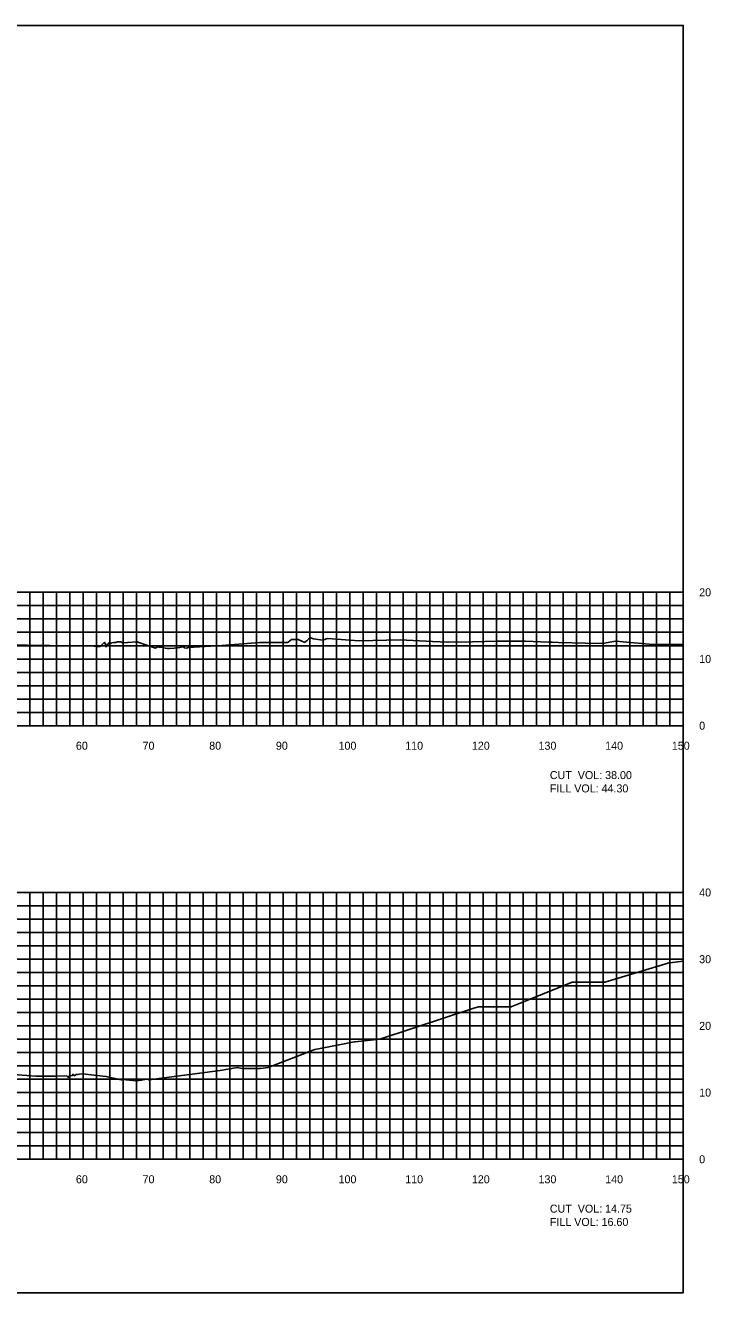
# Model space of a CAD drawing. Extents: x 1797645 to 1803805, y 248417 to 250269.
# Drawn here: x 1803702.3 to 1803805.1, y 250079.4 to 250269.4 of the extents above; entities that cross this region are included whole.
import ezdxf

# ---------------------------------------------------------------- set-up
doc = ezdxf.new("R2010")
doc.units = 0
for name, color, linetype in [('10', 7, 'Continuous'), ('31', 7, 'Continuous'), ('60', 7, 'Continuous'), ('ANNO-TXT', 7, 'Continuous'), ('Level 62', 7, 'Continuous'), ('M-ROADS', 7, 'Continuous')]:
    doc.layers.add(name, color=color, linetype=linetype)

msp = doc.modelspace()

# ---------------------------------------------------------------- linework, layer by layer
msp.add_lwpolyline([(1803501, 250079.43), (1803801, 250079.43), (1803801, 250269.43), (1803501, 250269.43)], close=True)
at = {"layer": '60'}
for p, q in [((1803801, 250164.43), (1803801, 250184.43)), ((1803801.06, 250184.43), (1803801, 250184.43)), ((1803801.06, 250174.43), (1803801, 250174.43)), ((1803501, 250164.43), (1803801, 250164.43)), ((1803711, 250164.37), (1803711, 250164.43)), ((1803721, 250164.37), (1803721, 250164.43)), ((1803731, 250164.37), (1803731, 250164.43)), ((1803741, 250164.37), (1803741, 250164.43)), ((1803751, 250164.37), (1803751, 250164.43)), ((1803761, 250164.37), (1803761, 250164.43)), ((1803771, 250164.37), (1803771, 250164.43)), ((1803781, 250164.37), (1803781, 250164.43)), ((1803791, 250164.37), (1803791, 250164.43)), ((1803801, 250164.37), (1803801, 250164.43)), ((1803801.06, 250164.43), (1803801, 250164.43)), ((1803801, 250099.43), (1803801, 250139.43)), ((1803801.06, 250139.43), (1803801, 250139.43)), ((1803801.06, 250129.43), (1803801, 250129.43)), ((1803801.06, 250119.43), (1803801, 250119.43)), ((1803801.06, 250109.43), (1803801, 250109.43)), ((1803501, 250099.43), (1803801, 250099.43)), ((1803711, 250099.37), (1803711, 250099.43)), ((1803721, 250099.37), (1803721, 250099.43)), ((1803731, 250099.37), (1803731, 250099.43)), ((1803741, 250099.37), (1803741, 250099.43)), ((1803751, 250099.37), (1803751, 250099.43)), ((1803761, 250099.37), (1803761, 250099.43)), ((1803771, 250099.37), (1803771, 250099.43)), ((1803781, 250099.37), (1803781, 250099.43)), ((1803791, 250099.37), (1803791, 250099.43)), ((1803801, 250099.37), (1803801, 250099.43)), ((1803801.06, 250099.43), (1803801, 250099.43))]:
    msp.add_line(p, q, dxfattribs=at)
at = {"layer": 'Level 62'}
for p, q in [((1803501, 250184.43), (1803801, 250184.43)), ((1803703, 250164.43), (1803703, 250184.43)), ((1803705, 250164.43), (1803705, 250184.43)), ((1803707, 250164.43), (1803707, 250184.43)), ((1803709, 250164.43), (1803709, 250184.43)), ((1803711, 250164.43), (1803711, 250184.43)), ((1803713, 250164.43), (1803713, 250184.43)), ((1803715, 250164.43), (1803715, 250184.43)), ((1803717, 250164.43), (1803717, 250184.43)), ((1803719, 250164.43), (1803719, 250184.43)), ((1803721, 250164.43), (1803721, 250184.43)), ((1803723, 250164.43), (1803723, 250184.43)), ((1803725, 250164.43), (1803725, 250184.43)), ((1803727, 250164.43), (1803727, 250184.43)), ((1803729, 250164.43), (1803729, 250184.43)), ((1803731, 250164.43), (1803731, 250184.43)), ((1803733, 250164.43), (1803733, 250184.43)), ((1803735, 250164.43), (1803735, 250184.43)), ((1803737, 250164.43), (1803737, 250184.43)), ((1803739, 250164.43), (1803739, 250184.43)), ((1803741, 250164.43), (1803741, 250184.43)), ((1803743, 250164.43), (1803743, 250184.43)), ((1803745, 250164.43), (1803745, 250184.43)), ((1803747, 250164.43), (1803747, 250184.43)), ((1803749, 250164.43), (1803749, 250184.43)), ((1803751, 250164.43), (1803751, 250184.43)), ((1803753, 250164.43), (1803753, 250184.43)), ((1803755, 250164.43), (1803755, 250184.43)), ((1803757, 250164.43), (1803757, 250184.43)), ((1803759, 250164.43), (1803759, 250184.43)), ((1803761, 250164.43), (1803761, 250184.43)), ((1803763, 250164.43), (1803763, 250184.43)), ((1803765, 250164.43), (1803765, 250184.43)), ((1803767, 250164.43), (1803767, 250184.43)), ((1803769, 250164.43), (1803769, 250184.43)), ((1803771, 250164.43), (1803771, 250184.43)), ((1803773, 250164.43), (1803773, 250184.43)), ((1803775, 250164.43), (1803775, 250184.43)), ((1803777, 250164.43), (1803777, 250184.43)), ((1803779, 250164.43), (1803779, 250184.43)), ((1803781, 250164.43), (1803781, 250184.43)), ((1803783, 250164.43), (1803783, 250184.43)), ((1803785, 250164.43), (1803785, 250184.43)), ((1803787, 250164.43), (1803787, 250184.43)), ((1803789, 250164.43), (1803789, 250184.43)), ((1803791, 250164.43), (1803791, 250184.43)), ((1803793, 250164.43), (1803793, 250184.43)), ((1803795, 250164.43), (1803795, 250184.43)), ((1803797, 250164.43), (1803797, 250184.43)), ((1803799, 250164.43), (1803799, 250184.43)), ((1803801, 250164.43), (1803801, 250184.43)), ((1803501, 250182.43), (1803801, 250182.43)), ((1803501, 250180.43), (1803801, 250180.43)), ((1803501, 250178.43), (1803801, 250178.43)), ((1803501, 250176.43), (1803801, 250176.43)), ((1803501, 250174.43), (1803801, 250174.43)), ((1803501, 250172.43), (1803801, 250172.43)), ((1803501, 250170.43), (1803801, 250170.43)), ((1803501, 250168.43), (1803801, 250168.43)), ((1803501, 250166.43), (1803801, 250166.43)), ((1803501, 250164.43), (1803801, 250164.43)), ((1803501, 250139.43), (1803801, 250139.43)), ((1803703, 250099.43), (1803703, 250139.43)), ((1803705, 250099.43), (1803705, 250139.43)), ((1803707, 250099.43), (1803707, 250139.43)), ((1803709, 250099.43), (1803709, 250139.43)), ((1803711, 250099.43), (1803711, 250139.43)), ((1803713, 250099.43), (1803713, 250139.43)), ((1803715, 250099.43), (1803715, 250139.43)), ((1803717, 250099.43), (1803717, 250139.43)), ((1803719, 250099.43), (1803719, 250139.43)), ((1803721, 250099.43), (1803721, 250139.43)), ((1803723, 250099.43), (1803723, 250139.43)), ((1803725, 250099.43), (1803725, 250139.43)), ((1803727, 250099.43), (1803727, 250139.43)), ((1803729, 250099.43), (1803729, 250139.43)), ((1803731, 250099.43), (1803731, 250139.43)), ((1803733, 250099.43), (1803733, 250139.43)), ((1803735, 250099.43), (1803735, 250139.43)), ((1803737, 250099.43), (1803737, 250139.43)), ((1803739, 250099.43), (1803739, 250139.43)), ((1803741, 250099.43), (1803741, 250139.43)), ((1803743, 250099.43), (1803743, 250139.43)), ((1803745, 250099.43), (1803745, 250139.43)), ((1803747, 250099.43), (1803747, 250139.43)), ((1803749, 250099.43), (1803749, 250139.43)), ((1803751, 250099.43), (1803751, 250139.43)), ((1803753, 250099.43), (1803753, 250139.43)), ((1803755, 250099.43), (1803755, 250139.43)), ((1803757, 250099.43), (1803757, 250139.43)), ((1803759, 250099.43), (1803759, 250139.43)), ((1803761, 250099.43), (1803761, 250139.43)), ((1803763, 250099.43), (1803763, 250139.43)), ((1803765, 250099.43), (1803765, 250139.43)), ((1803767, 250099.43), (1803767, 250139.43)), ((1803769, 250099.43), (1803769, 250139.43)), ((1803771, 250099.43), (1803771, 250139.43)), ((1803773, 250099.43), (1803773, 250139.43)), ((1803775, 250099.43), (1803775, 250139.43)), ((1803777, 250099.43), (1803777, 250139.43)), ((1803779, 250099.43), (1803779, 250139.43)), ((1803781, 250099.43), (1803781, 250139.43)), ((1803783, 250099.43), (1803783, 250139.43)), ((1803785, 250099.43), (1803785, 250139.43)), ((1803787, 250099.43), (1803787, 250139.43)), ((1803789, 250099.43), (1803789, 250139.43)), ((1803791, 250099.43), (1803791, 250139.43)), ((1803793, 250099.43), (1803793, 250139.43)), ((1803795, 250099.43), (1803795, 250139.43)), ((1803797, 250099.43), (1803797, 250139.43)), ((1803799, 250099.43), (1803799, 250139.43)), ((1803801, 250099.43), (1803801, 250139.43)), ((1803501, 250137.43), (1803801, 250137.43)), ((1803501, 250135.43), (1803801, 250135.43)), ((1803501, 250133.43), (1803801, 250133.43)), ((1803501, 250131.43), (1803801, 250131.43)), ((1803501, 250129.43), (1803801, 250129.43)), ((1803501, 250127.43), (1803801, 250127.43)), ((1803501, 250125.43), (1803801, 250125.43)), ((1803501, 250123.43), (1803801, 250123.43)), ((1803501, 250121.43), (1803801, 250121.43)), ((1803501, 250119.43), (1803801, 250119.43)), ((1803501, 250117.43), (1803801, 250117.43)), ((1803501, 250115.43), (1803801, 250115.43)), ((1803501, 250113.43), (1803801, 250113.43)), ((1803501, 250111.43), (1803801, 250111.43)), ((1803501, 250109.43), (1803801, 250109.43)), ((1803501, 250107.43), (1803801, 250107.43)), ((1803501, 250105.43), (1803801, 250105.43)), ((1803501, 250103.43), (1803801, 250103.43)), ((1803501, 250101.43), (1803801, 250101.43)), ((1803501, 250099.43), (1803801, 250099.43))]:
    msp.add_line(p, q, dxfattribs=at)
at = {"layer": 'M-ROADS'}
for points in [[(1803700.07, 250176.49), (1803702.33, 250176.49), (1803702.46, 250176.49), (1803702.5, 250176.49), (1803702.61, 250176.49), (1803709.46, 250176.4), (1803711.42, 250176.41), (1803711.61, 250176.41), (1803711.66, 250176.41), (1803712.1, 250176.4), (1803713.13, 250176.33), (1803713.52, 250176.32), (1803714.18, 250176.94), (1803714.42, 250176.4), (1803714.43, 250176.37), (1803714.43, 250176.24), (1803714.44, 250176.27), (1803714.44, 250176.4), (1803714.45, 250176.44), (1803714.5, 250176.37), (1803714.63, 250176.66), (1803714.83, 250176.86), (1803714.84, 250176.85), (1803714.93, 250176.54), (1803715.07, 250176.79), (1803715.14, 250176.79), (1803715.15, 250176.81), (1803715.22, 250176.81), (1803715.31, 250176.85), (1803715.61, 250176.9), (1803715.85, 250176.93), (1803716.15, 250176.99), (1803716.63, 250177), (1803716.63, 250177), (1803716.64, 250177), (1803716.89, 250176.88), (1803717.62, 250176.91), (1803718.98, 250176.99), (1803719.16, 250176.99), (1803719.33, 250176.92), (1803721.83, 250176.08), (1803722.03, 250176.19), (1803722.15, 250176.28), (1803722.16, 250176.25), (1803722.36, 250176.22), (1803722.87, 250176.18), (1803723.33, 250176.04), (1803723.65, 250176.02), (1803723.94, 250176.02), (1803724.66, 250176.08), (1803725.18, 250176.13), (1803726.03, 250176.24), (1803726.07, 250176.25), (1803726.08, 250176.29), (1803726.09, 250176.26), (1803726.19, 250176.1), (1803726.56, 250176.08), (1803726.72, 250176.18), (1803731.82, 250176.44), (1803737.42, 250176.9), (1803739.05, 250176.9), (1803739.11, 250176.9), (1803739.25, 250176.9), (1803739.61, 250176.92), (1803739.96, 250176.92), (1803740.15, 250176.93), (1803741.66, 250176.9), (1803741.71, 250176.92), (1803741.75, 250176.94), (1803742.22, 250177.34), (1803743.26, 250177.38), (1803743.78, 250177.11), (1803744.22, 250176.91), (1803744.28, 250177), (1803744.55, 250177.18), (1803745.01, 250177.64), (1803745.56, 250177.47), (1803746.95, 250177.27), (1803747.65, 250177.49), (1803752.39, 250177.15), (1803758.52, 250177.3), (1803763.37, 250177.04), (1803765.7, 250176.94), (1803765.71, 250176.95), (1803765.76, 250176.94), (1803769.4, 250176.99), (1803773.17, 250177.12), (1803775.74, 250177.13), (1803777.35, 250177.11), (1803780.81, 250176.95), (1803781.08, 250176.95), (1803781.33, 250176.95), (1803782.31, 250176.91), (1803786.36, 250176.83), (1803788.88, 250176.78), (1803790.86, 250177.09), (1803791.98, 250176.99), (1803796.46, 250176.61), (1803798.82, 250176.6), (1803801, 250176.59)], [(1803698.45, 250112.3), (1803703.89, 250111.88), (1803705.6, 250111.89), (1803706.12, 250111.89), (1803706.25, 250111.89), (1803706.55, 250111.88), (1803706.69, 250111.89), (1803706.87, 250111.87), (1803708.55, 250111.93), (1803708.75, 250111.72), (1803708.75, 250111.65), (1803708.76, 250111.72), (1803708.77, 250111.74), (1803708.77, 250111.74), (1803708.79, 250111.78), (1803708.81, 250111.82), (1803708.84, 250111.85), (1803708.86, 250111.88), (1803708.97, 250111.92), (1803709.36, 250111.98), (1803709.44, 250112.18), (1803709.49, 250112.1), (1803709.73, 250111.96), (1803709.89, 250112.16), (1803710.12, 250112.16), (1803710.44, 250112.17), (1803710.87, 250112.24), (1803714.4, 250111.85), (1803716.67, 250111.34), (1803716.74, 250111.34), (1803716.97, 250111.42), (1803717.38, 250111.35), (1803717.59, 250111.34), (1803717.94, 250111.31), (1803718.95, 250111.21), (1803719.76, 250111.31), (1803719.94, 250111.32), (1803720.67, 250111.42), (1803720.82, 250111.34), (1803731.54, 250112.74), (1803734.13, 250113.19), (1803734.78, 250113.05), (1803736.06, 250113.05), (1803737.57, 250113.05), (1803738.75, 250113.19), (1803745.72, 250115.89), (1803747.33, 250116.2), (1803751.62, 250117.02), (1803751.7, 250117.02), (1803751.79, 250117.02), (1803755.48, 250117.44), (1803769.73, 250122.14), (1803770.31, 250122.28), (1803770.64, 250122.3), (1803772.73, 250122.3), (1803775.17, 250122.3), (1803775.22, 250122.3), (1803775.28, 250122.32), (1803777.8, 250123.34), (1803784.33, 250125.98), (1803784.48, 250125.98), (1803786.82, 250125.98), (1803788.82, 250125.98), (1803789.26, 250125.98), (1803798.39, 250128.71), (1803798.85, 250128.86), (1803798.99, 250128.88), (1803801, 250129.14)]]:
    msp.add_lwpolyline(points, dxfattribs=at)

# ---------------------------------------------------------------- texts
at = {"layer": '10'}
for s, p in [('60', (1803709.9, 250160.83)), ('70', (1803719.9, 250160.83)), ('80', (1803729.9, 250160.83)), ('90', (1803739.9, 250160.83)), ('100', (1803749.3, 250160.83)), ('110', (1803759.3, 250160.83)), ('120', (1803769.3, 250160.83)), ('130', (1803779.3, 250160.83)), ('140', (1803789.3, 250160.83)), ('150', (1803799.3, 250160.83)), ('60', (1803709.9, 250095.83)), ('70', (1803719.9, 250095.83)), ('80', (1803729.9, 250095.83)), ('90', (1803739.9, 250095.83)), ('100', (1803749.3, 250095.83)), ('110', (1803759.3, 250095.83)), ('120', (1803769.3, 250095.83)), ('130', (1803779.3, 250095.83)), ('140', (1803789.3, 250095.83)), ('150', (1803799.3, 250095.83))]:
    msp.add_text(s, height=1.2, dxfattribs=at).set_placement(p)
at = {"layer": '31'}
for s, p in [('20', (1803803.4, 250183.83)), ('10', (1803803.4, 250173.83)), ('0', (1803803.4, 250163.83)), ('40', (1803803.4, 250138.83)), ('30', (1803803.4, 250128.83)), ('20', (1803803.4, 250118.83)), ('10', (1803803.4, 250108.83)), ('0', (1803803.4, 250098.83))]:
    msp.add_text(s, height=1.2, dxfattribs=at).set_placement(p)
at = {"layer": 'ANNO-TXT'}
for s, p in [('CUT  VOL: 38.00', (1803781, 250156.43)), ('FILL VOL: 44.30', (1803781, 250154.43)), ('CUT  VOL: 14.75', (1803781, 250091.43)), ('FILL VOL: 16.60', (1803781, 250089.43))]:
    msp.add_text(s, height=1.2, dxfattribs=at).set_placement(p)

doc.saveas('drawing.dxf')
